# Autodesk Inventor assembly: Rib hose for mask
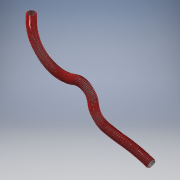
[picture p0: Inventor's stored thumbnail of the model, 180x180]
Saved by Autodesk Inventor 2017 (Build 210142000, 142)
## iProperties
Created: 2020-03
Part Number: Rib hose for mask
Document SubType Name: Assembly
Designer: user
Author: user
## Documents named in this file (3)
- C:\Users\user\Documents\Inventor\Home Ventilator CPAP\Rib hose for mask.iam
- C:\Users\user\Documents\Inventor\Home Ventilator CPAP\hose for mask.ipt
- C:\Users\user\Documents\Inventor\Home Ventilator CPAP\Ring for hose.ipt
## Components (181 placed, 2 different names)
1. hose for mask:1 — Mate:1, Angle:1
2. Ring for hose:1 — Mate:1, Angle:1
3. Ring for hose:2
4. Ring for hose:3
5. Ring for hose:4
6. Ring for hose:5
7. Ring for hose:6
8. Ring for hose:7
9. Ring for hose:8
10. Ring for hose:9
11. Ring for hose:10
12. Ring for hose:11
13. Ring for hose:12
14. Ring for hose:13
15. Ring for hose:14
16. Ring for hose:15
17. Ring for hose:16
18. Ring for hose:17
19. Ring for hose:18
20. Ring for hose:19
21. Ring for hose:20
22. Ring for hose:21
23. Ring for hose:22
24. Ring for hose:23
25. Ring for hose:24
26. Ring for hose:25
27. Ring for hose:26
28. Ring for hose:27
29. Ring for hose:28
30. Ring for hose:29
31. Ring for hose:30
32. Ring for hose:31
33. Ring for hose:32
34. Ring for hose:33
35. Ring for hose:34
36. Ring for hose:35
37. Ring for hose:36
38. Ring for hose:37
39. Ring for hose:38
40. Ring for hose:39
41. Ring for hose:40
42. Ring for hose:41
43. Ring for hose:42
44. Ring for hose:43
45. Ring for hose:44
46. Ring for hose:45
47. Ring for hose:46
48. Ring for hose:47
49. Ring for hose:48
50. Ring for hose:49
51. Ring for hose:50
52. Ring for hose:51
53. Ring for hose:52
54. Ring for hose:53
55. Ring for hose:54
56. Ring for hose:55
57. Ring for hose:56
58. Ring for hose:57
59. Ring for hose:58
60. Ring for hose:59
61. Ring for hose:60
62. Ring for hose:61
63. Ring for hose:62
64. Ring for hose:63
65. Ring for hose:64
66. Ring for hose:65
67. Ring for hose:66
68. Ring for hose:67
69. Ring for hose:68
70. Ring for hose:69
71. Ring for hose:70
72. Ring for hose:71
73. Ring for hose:72
74. Ring for hose:73
75. Ring for hose:74
76. Ring for hose:75
77. Ring for hose:76
78. Ring for hose:77
79. Ring for hose:78
80. Ring for hose:79
81. Ring for hose:80
82. Ring for hose:81
83. Ring for hose:82
84. Ring for hose:83
85. Ring for hose:84
86. Ring for hose:85
87. Ring for hose:86
88. Ring for hose:87
89. Ring for hose:88
90. Ring for hose:89
91. Ring for hose:90
92. Ring for hose:91
93. Ring for hose:92
94. Ring for hose:93
95. Ring for hose:94
96. Ring for hose:95
97. Ring for hose:96
98. Ring for hose:97
99. Ring for hose:98
100. Ring for hose:99
101. Ring for hose:100
102. Ring for hose:101
103. Ring for hose:102
104. Ring for hose:103
105. Ring for hose:104
106. Ring for hose:105
107. Ring for hose:106
108. Ring for hose:107
109. Ring for hose:108
110. Ring for hose:109
111. Ring for hose:110
112. Ring for hose:111
113. Ring for hose:112
114. Ring for hose:113
115. Ring for hose:114
116. Ring for hose:115
117. Ring for hose:116
118. Ring for hose:117
119. Ring for hose:118
120. Ring for hose:119
121. Ring for hose:120
122. Ring for hose:121
123. Ring for hose:122
124. Ring for hose:123
125. Ring for hose:124
126. Ring for hose:125
127. Ring for hose:126
128. Ring for hose:127
129. Ring for hose:128
130. Ring for hose:129
131. Ring for hose:130
132. Ring for hose:131
133. Ring for hose:132
134. Ring for hose:133
135. Ring for hose:134
136. Ring for hose:135
137. Ring for hose:136
138. Ring for hose:137
139. Ring for hose:138
140. Ring for hose:139
141. Ring for hose:140
142. Ring for hose:141
143. Ring for hose:142
144. Ring for hose:143
145. Ring for hose:144
146. Ring for hose:145
147. Ring for hose:146
148. Ring for hose:147
149. Ring for hose:148
150. Ring for hose:149
151. Ring for hose:150
152. Ring for hose:151
153. Ring for hose:152
154. Ring for hose:153
155. Ring for hose:154
156. Ring for hose:155
157. Ring for hose:156
158. Ring for hose:157
159. Ring for hose:158
160. Ring for hose:159
161. Ring for hose:160
162. Ring for hose:161
163. Ring for hose:162
164. Ring for hose:163
165. Ring for hose:164
166. Ring for hose:165
167. Ring for hose:166
168. Ring for hose:167
169. Ring for hose:168
170. Ring for hose:169
171. Ring for hose:170
172. Ring for hose:171
173. Ring for hose:172
174. Ring for hose:173
175. Ring for hose:174
176. Ring for hose:175
177. Ring for hose:176
178. Ring for hose:177
179. Ring for hose:178
180. Ring for hose:179
181. Ring for hose:180
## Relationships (2: Mate 1, Angle 1)
- Mate:1: hose for mask:1 ↔ Ring for hose:1
- Angle:1: hose for mask:1 ↔ Ring for hose:1
